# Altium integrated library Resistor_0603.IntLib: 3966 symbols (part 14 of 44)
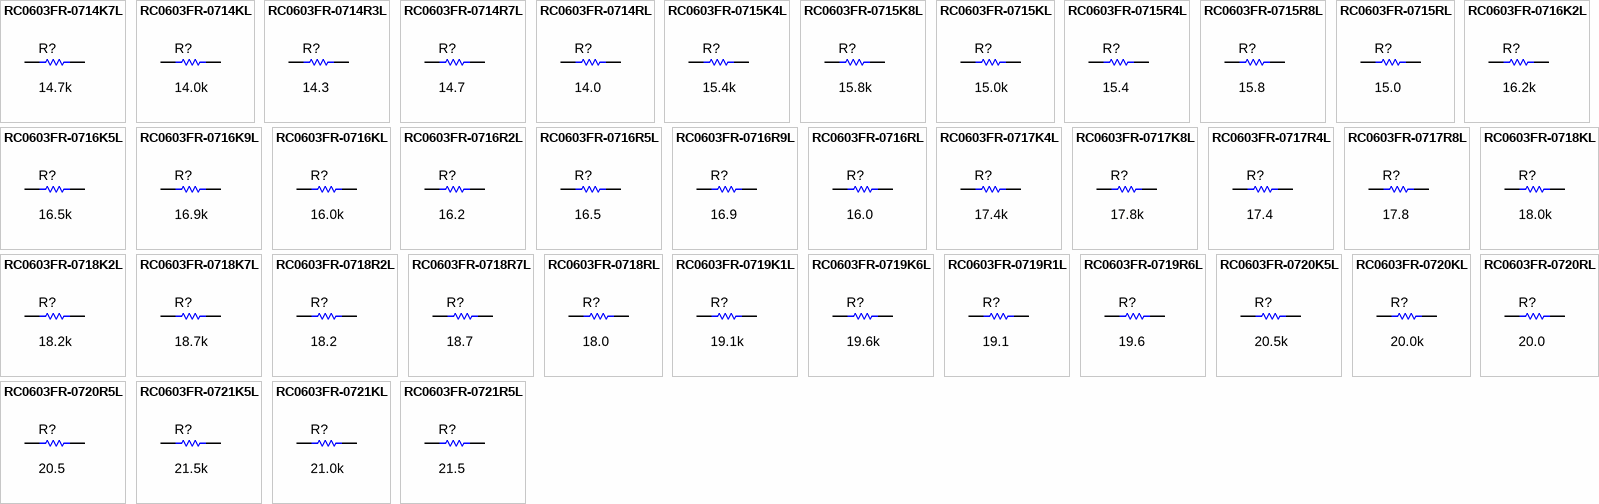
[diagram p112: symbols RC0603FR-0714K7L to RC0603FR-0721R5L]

## RC0603FR-0715K8L
designator R?  ValueDisplayed: 15.8k  (hidden comment: RC0603FR-0715K8L)
RES, 15.8 k, 1%, 0.1 W, 0603; Manufacturer: Yageo America; CompType: Resistor; Value: 15.8k; Res_ohm: 15800; Value_Code: 15k8; Tolerance_%: 1; Power_W: 0.1; Value2: 0.1W; VDC_V: 150; TempCo: 200 ppm/C; SizeArea_mm2: 1.28; SizeX_mm: 1.6; SizeY_mm: 0.8; EIA_Code: E96; U/M: EA; AEC Category: Q200
signal-integrity model Resistor
simulation model Resistor
footprint 0603
footprint 0603M
footprint 0603L
footprint 0603_HV
footprint 0603S
pins: 1, 2

## RC0603FR-0715KL
designator R?  ValueDisplayed: 15.0k  (hidden comment: RC0603FR-0715KL)
RES, 15.0 k, 1%, 0.1 W, 0603; Manufacturer: Yageo America; CompType: Resistor; Value: 15.0k; Res_ohm: 15000; Value_Code: 15k0; Tolerance_%: 1; Power_W: 0.1; Value2: 0.1W; VDC_V: 150; TempCo: 200 ppm/C; SizeArea_mm2: 1.28; SizeX_mm: 1.6; SizeY_mm: 0.8; EIA_Code: E96; U/M: EA; AEC Category: Q200; Green_Lifecycle: Active; Green_REACh: Passed
signal-integrity model Resistor
simulation model Resistor
footprint 0603
footprint 0603M
footprint 0603L
footprint 0603_HV
footprint 0603S
pins: 1, 2

## RC0603FR-0715R4L
designator R?  ValueDisplayed: 15.4  (hidden comment: RC0603FR-0715R4L)
RES, 15.4, 1%, 0.1 W, 0603; Manufacturer: Yageo America; CompType: Resistor; Value: 15.4; Value_Code: 15R4; Tolerance_%: 1; Power_W: 0.1; Value2: 0.1W; VDC_V: 150; TempCo: 200 ppm/C; SizeArea_mm2: 1.28; SizeX_mm: 1.6; SizeY_mm: 0.8; EIA_Code: E96; U/M: EA; AEC Category: Q200
signal-integrity model Resistor
simulation model Resistor
footprint 0603
footprint 0603M
footprint 0603L
footprint 0603_HV
footprint 0603S
pins: 1, 2

## RC0603FR-0715R8L
designator R?  ValueDisplayed: 15.8  (hidden comment: RC0603FR-0715R8L)
RES, 15.8, 1%, 0.1 W, 0603; Manufacturer: Yageo America; CompType: Resistor; Value: 15.8; Value_Code: 15R8; Tolerance_%: 1; Power_W: 0.1; Value2: 0.1W; VDC_V: 150; TempCo: 200 ppm/C; SizeArea_mm2: 1.28; SizeX_mm: 1.6; SizeY_mm: 0.8; EIA_Code: E96; U/M: EA; AEC Category: Q200
signal-integrity model Resistor
simulation model Resistor
footprint 0603
footprint 0603M
footprint 0603L
footprint 0603_HV
footprint 0603S
pins: 1, 2

## RC0603FR-0715RL
designator R?  ValueDisplayed: 15.0  (hidden comment: RC0603FR-0715RL)
RES, 15.0, 1%, 0.1 W, 0603; Manufacturer: Yageo America; CompType: Resistor; Value: 15.0; Res_ohm: 15; Value_Code: 15R0; Tolerance_%: 1; Power_W: 0.1; Value2: 0.1W; VDC_V: 150; TempCo: 200 ppm/C; SizeArea_mm2: 1.28; SizeX_mm: 1.6; SizeY_mm: 0.8; EIA_Code: E96; U/M: EA; AEC Category: Q200; Green_Lifecycle: Not Set; Green_REACh: Incomplete
signal-integrity model Resistor
simulation model Resistor
footprint 0603
footprint 0603M
footprint 0603L
footprint 0603_HV
footprint 0603S
pins: 1, 2

## RC0603FR-0716K2L
designator R?  ValueDisplayed: 16.2k  (hidden comment: RC0603FR-0716K2L)
RES, 16.2 k, 1%, 0.1 W, 0603; Manufacturer: Yageo America; CompType: Resistor; Value: 16.2k; Res_ohm: 16200; Value_Code: 16k2; Tolerance_%: 1; Power_W: 0.1; Value2: 0.1W; VDC_V: 150; TempCo: 200 ppm/C; SizeArea_mm2: 1.28; SizeX_mm: 1.6; SizeY_mm: 0.8; EIA_Code: E96; U/M: EA; AEC Category: Q200; Green_Lifecycle: Active; Green_REACh: Passed
signal-integrity model Resistor
simulation model Resistor
footprint 0603
footprint 0603M
footprint 0603L
footprint 0603_HV
footprint 0603S
pins: 1, 2

## RC0603FR-0716K5L
designator R?  ValueDisplayed: 16.5k  (hidden comment: RC0603FR-0716K5L)
RES, 16.5 k, 1%, 0.1 W, 0603; Manufacturer: Yageo America; CompType: Resistor; Value: 16.5k; Res_ohm: 16500; Value_Code: 16k5; Tolerance_%: 1; Power_W: 0.1; Value2: 0.1W; VDC_V: 150; TempCo: 200 ppm/C; SizeArea_mm2: 1.28; SizeX_mm: 1.6; SizeY_mm: 0.8; EIA_Code: E96; U/M: EA; AEC Category: Q200; Green_Lifecycle: Active; Green_REACh: Passed
signal-integrity model Resistor
simulation model Resistor
footprint 0603
footprint 0603M
footprint 0603L
footprint 0603_HV
footprint 0603S
pins: 1, 2

## RC0603FR-0716K9L
designator R?  ValueDisplayed: 16.9k  (hidden comment: RC0603FR-0716K9L)
RES, 16.9 k, 1%, 0.1 W, 0603; Manufacturer: Yageo America; CompType: Resistor; Value: 16.9k; Res_ohm: 16900; Value_Code: 16k9; Tolerance_%: 1; Power_W: 0.1; Value2: 0.1W; VDC_V: 150; TempCo: 200 ppm/C; SizeArea_mm2: 1.28; SizeX_mm: 1.6; SizeY_mm: 0.8; EIA_Code: E96; U/M: EA; AEC Category: Q200; Green_Lifecycle: Active; Green_REACh: Passed
signal-integrity model Resistor
simulation model Resistor
footprint 0603
footprint 0603M
footprint 0603L
footprint 0603_HV
footprint 0603S
pins: 1, 2

## RC0603FR-0716KL
designator R?  ValueDisplayed: 16.0k  (hidden comment: RC0603FR-0716KL)
RES, 16.0 k, 1%, 0.1 W, 0603; Manufacturer: Yageo America; CompType: Resistor; Value: 16.0k; Res_ohm: 16000; Value_Code: 16k0; Tolerance_%: 1; Power_W: 0.1; Value2: 0.1W; VDC_V: 150; TempCo: 200 ppm/C; SizeArea_mm2: 1.28; SizeX_mm: 1.6; SizeY_mm: 0.8; U/M: EA; AEC Category: Q200; Green_Lifecycle: Active; Green_REACh: Passed
signal-integrity model Resistor
simulation model Resistor
footprint 0603
footprint 0603M
footprint 0603L
footprint 0603_HV
footprint 0603S
pins: 1, 2

## RC0603FR-0716R2L
designator R?  ValueDisplayed: 16.2  (hidden comment: RC0603FR-0716R2L)
RES, 16.2, 1%, 0.1 W, 0603; Manufacturer: Yageo America; CompType: Resistor; Value: 16.2; Value_Code: 16R2; Tolerance_%: 1; Power_W: 0.1; Value2: 0.1W; VDC_V: 150; TempCo: 200 ppm/C; SizeArea_mm2: 1.28; SizeX_mm: 1.6; SizeY_mm: 0.8; EIA_Code: E96; U/M: EA; AEC Category: Q200
signal-integrity model Resistor
simulation model Resistor
footprint 0603
footprint 0603M
footprint 0603L
footprint 0603_HV
footprint 0603S
pins: 1, 2

## RC0603FR-0716R5L
designator R?  ValueDisplayed: 16.5  (hidden comment: RC0603FR-0716R5L)
RES, 16.5, 1%, 0.1 W, 0603; Manufacturer: Yageo America; CompType: Resistor; Value: 16.5; Value_Code: 16R5; Tolerance_%: 1; Power_W: 0.1; Value2: 0.1W; VDC_V: 150; TempCo: 200 ppm/C; SizeArea_mm2: 1.28; SizeX_mm: 1.6; SizeY_mm: 0.8; EIA_Code: E96; U/M: EA; AEC Category: Q200
signal-integrity model Resistor
simulation model Resistor
footprint 0603
footprint 0603M
footprint 0603L
footprint 0603_HV
footprint 0603S
pins: 1, 2

## RC0603FR-0716R9L
designator R?  ValueDisplayed: 16.9  (hidden comment: RC0603FR-0716R9L)
RES, 16.9, 1%, 0.1 W, 0603; Manufacturer: Yageo America; CompType: Resistor; Value: 16.9; Value_Code: 16R9; Tolerance_%: 1; Power_W: 0.1; Value2: 0.1W; VDC_V: 150; TempCo: 200 ppm/C; SizeArea_mm2: 1.28; SizeX_mm: 1.6; SizeY_mm: 0.8; EIA_Code: E96; U/M: EA; AEC Category: Q200
signal-integrity model Resistor
simulation model Resistor
footprint 0603
footprint 0603M
footprint 0603L
footprint 0603_HV
footprint 0603S
pins: 1, 2

## RC0603FR-0716RL
designator R?  ValueDisplayed: 16.0  (hidden comment: RC0603FR-0716RL)
RES, 16.0, 1%, 0.1 W, 0603; Manufacturer: Yageo America; CompType: Resistor; Value: 16.0; Res_ohm: 16; Value_Code: 16R0; Tolerance_%: 1; Power_W: 0.1; Value2: 0.1W; VDC_V: 150; TempCo: 200 ppm/C; SizeArea_mm2: 1.28; SizeX_mm: 1.6; SizeY_mm: 0.8; U/M: EA; AEC Category: Q200
signal-integrity model Resistor
simulation model Resistor
footprint 0603
footprint 0603M
footprint 0603L
footprint 0603_HV
footprint 0603S
pins: 1, 2

## RC0603FR-0717K4L
designator R?  ValueDisplayed: 17.4k  (hidden comment: RC0603FR-0717K4L)
RES, 17.4 k, 1%, 0.1 W, 0603; Manufacturer: Yageo America; CompType: Resistor; Value: 17.4k; Res_ohm: 17400; Value_Code: 17k4; Tolerance_%: 1; Power_W: 0.1; Value2: 0.1W; VDC_V: 150; TempCo: 200 ppm/C; SizeArea_mm2: 1.28; SizeX_mm: 1.6; SizeY_mm: 0.8; EIA_Code: E96; U/M: EA; AEC Category: Q200; Green_Lifecycle: Active; Green_REACh: Passed
signal-integrity model Resistor
simulation model Resistor
footprint 0603
footprint 0603M
footprint 0603L
footprint 0603_HV
footprint 0603S
pins: 1, 2

## RC0603FR-0717K8L
designator R?  ValueDisplayed: 17.8k  (hidden comment: RC0603FR-0717K8L)
RES, 17.8 k, 1%, 0.1 W, 0603; Manufacturer: Yageo America; CompType: Resistor; Value: 17.8k; Res_ohm: 17800; Value_Code: 17k8; Tolerance_%: 1; Power_W: 0.1; Value2: 0.1W; VDC_V: 150; TempCo: 200 ppm/C; SizeArea_mm2: 1.28; SizeX_mm: 1.6; SizeY_mm: 0.8; EIA_Code: E96; U/M: EA; AEC Category: Q200
signal-integrity model Resistor
simulation model Resistor
footprint 0603
footprint 0603M
footprint 0603L
footprint 0603_HV
footprint 0603S
pins: 1, 2

## RC0603FR-0717R4L
designator R?  ValueDisplayed: 17.4  (hidden comment: RC0603FR-0717R4L)
RES, 17.4, 1%, 0.1 W, 0603; Manufacturer: Yageo America; CompType: Resistor; Value: 17.4; Value_Code: 17R4; Tolerance_%: 1; Power_W: 0.1; Value2: 0.1W; VDC_V: 150; TempCo: 200 ppm/C; SizeArea_mm2: 1.28; SizeX_mm: 1.6; SizeY_mm: 0.8; EIA_Code: E96; U/M: EA; AEC Category: Q200; Green_Lifecycle: Active; Green_REACh: Passed
signal-integrity model Resistor
simulation model Resistor
footprint 0603
footprint 0603M
footprint 0603L
footprint 0603_HV
footprint 0603S
pins: 1, 2

## RC0603FR-0717R8L
designator R?  ValueDisplayed: 17.8  (hidden comment: RC0603FR-0717R8L)
RES, 17.8, 1%, 0.1 W, 0603; Manufacturer: Yageo America; CompType: Resistor; Value: 17.8; Value_Code: 17R8; Tolerance_%: 1; Power_W: 0.1; Value2: 0.1W; VDC_V: 150; TempCo: 200 ppm/C; SizeArea_mm2: 1.28; SizeX_mm: 1.6; SizeY_mm: 0.8; EIA_Code: E96; U/M: EA; AEC Category: Q200
signal-integrity model Resistor
simulation model Resistor
footprint 0603
footprint 0603M
footprint 0603L
footprint 0603_HV
footprint 0603S
pins: 1, 2

## RC0603FR-0718K2L
designator R?  ValueDisplayed: 18.2k  (hidden comment: RC0603FR-0718K2L)
RES, 18.2 k, 1%, 0.1 W, 0603; Manufacturer: Yageo America; CompType: Resistor; Value: 18.2k; Res_ohm: 18200; Value_Code: 18k2; Tolerance_%: 1; Power_W: 0.1; Value2: 0.1W; VDC_V: 150; TempCo: 200 ppm/C; SizeArea_mm2: 1.28; SizeX_mm: 1.6; SizeY_mm: 0.8; EIA_Code: E96; U/M: EA; AEC Category: Q200; Green_Lifecycle: Active; Green_REACh: Passed
signal-integrity model Resistor
simulation model Resistor
footprint 0603
footprint 0603M
footprint 0603L
footprint 0603_HV
footprint 0603S
pins: 1, 2

## RC0603FR-0718K7L
designator R?  ValueDisplayed: 18.7k  (hidden comment: RC0603FR-0718K7L)
RES, 18.7 k, 1%, 0.1 W, 0603; Manufacturer: Yageo America; CompType: Resistor; Value: 18.7k; Res_ohm: 18700; Value_Code: 18k7; Tolerance_%: 1; Power_W: 0.1; Value2: 0.1W; VDC_V: 150; TempCo: 200 ppm/C; SizeArea_mm2: 1.28; SizeX_mm: 1.6; SizeY_mm: 0.8; EIA_Code: E96; U/M: EA; AEC Category: Q200
signal-integrity model Resistor
simulation model Resistor
footprint 0603
footprint 0603M
footprint 0603L
footprint 0603_HV
footprint 0603S
pins: 1, 2

## RC0603FR-0718KL
designator R?  ValueDisplayed: 18.0k  (hidden comment: RC0603FR-0718KL)
RES, 18.0 k, 1%, 0.1 W, 0603; Manufacturer: Yageo America; CompType: Resistor; Value: 18.0k; Res_ohm: 18000; Value_Code: 18k0; Tolerance_%: 1; Power_W: 0.1; Value2: 0.1W; VDC_V: 150; TempCo: 200 ppm/C; SizeArea_mm2: 1.28; SizeX_mm: 1.6; SizeY_mm: 0.8; U/M: EA; AEC Category: Q200; Green_Lifecycle: Active; Green_REACh: Passed
signal-integrity model Resistor
simulation model Resistor
footprint 0603
footprint 0603M
footprint 0603L
footprint 0603_HV
footprint 0603S
pins: 1, 2

## RC0603FR-0718R2L
designator R?  ValueDisplayed: 18.2  (hidden comment: RC0603FR-0718R2L)
RES, 18.2, 1%, 0.1 W, 0603; Manufacturer: Yageo America; CompType: Resistor; Value: 18.2; Value_Code: 18R2; Tolerance_%: 1; Power_W: 0.1; Value2: 0.1W; VDC_V: 150; TempCo: 200 ppm/C; SizeArea_mm2: 1.28; SizeX_mm: 1.6; SizeY_mm: 0.8; EIA_Code: E96; U/M: EA; AEC Category: Q200
signal-integrity model Resistor
simulation model Resistor
footprint 0603
footprint 0603M
footprint 0603L
footprint 0603_HV
footprint 0603S
pins: 1, 2

## RC0603FR-0718R7L
designator R?  ValueDisplayed: 18.7  (hidden comment: RC0603FR-0718R7L)
RES, 18.7, 1%, 0.1 W, 0603; Manufacturer: Yageo America; CompType: Resistor; Value: 18.7; Value_Code: 18R7; Tolerance_%: 1; Power_W: 0.1; Value2: 0.1W; VDC_V: 150; TempCo: 200 ppm/C; SizeArea_mm2: 1.28; SizeX_mm: 1.6; SizeY_mm: 0.8; EIA_Code: E96; U/M: EA; AEC Category: Q200
signal-integrity model Resistor
simulation model Resistor
footprint 0603
footprint 0603M
footprint 0603L
footprint 0603_HV
footprint 0603S
pins: 1, 2

## RC0603FR-0718RL
designator R?  ValueDisplayed: 18.0  (hidden comment: RC0603FR-0718RL)
RES, 18.0, 1%, 0.1 W, 0603; Manufacturer: Yageo America; CompType: Resistor; Value: 18.0; Res_ohm: 18; Value_Code: 18R0; Tolerance_%: 1; Power_W: 0.1; Value2: 0.1W; VDC_V: 150; TempCo: 200 ppm/C; SizeArea_mm2: 1.28; SizeX_mm: 1.6; SizeY_mm: 0.8; U/M: EA; AEC Category: Q200
signal-integrity model Resistor
simulation model Resistor
footprint 0603
footprint 0603M
footprint 0603L
footprint 0603_HV
footprint 0603S
pins: 1, 2

## RC0603FR-0719K1L
designator R?  ValueDisplayed: 19.1k  (hidden comment: RC0603FR-0719K1L)
RES, 19.1 k, 1%, 0.1 W, 0603; Manufacturer: Yageo America; CompType: Resistor; Value: 19.1k; Res_ohm: 19100; Value_Code: 19k1; Tolerance_%: 1; Power_W: 0.1; Value2: 0.1W; VDC_V: 150; TempCo: 200 ppm/C; SizeArea_mm2: 1.28; SizeX_mm: 1.6; SizeY_mm: 0.8; EIA_Code: E96; U/M: EA; AEC Category: Q200
signal-integrity model Resistor
simulation model Resistor
footprint 0603
footprint 0603M
footprint 0603L
footprint 0603_HV
footprint 0603S
pins: 1, 2

## RC0603FR-0719K6L
designator R?  ValueDisplayed: 19.6k  (hidden comment: RC0603FR-0719K6L)
RES, 19.6 k, 1%, 0.1 W, 0603; Manufacturer: Yageo America; CompType: Resistor; Value: 19.6k; Res_ohm: 19600; Value_Code: 19k6; Tolerance_%: 1; Power_W: 0.1; Value2: 0.1W; VDC_V: 150; TempCo: 200 ppm/C; SizeArea_mm2: 1.28; SizeX_mm: 1.6; SizeY_mm: 0.8; EIA_Code: E96; U/M: EA; AEC Category: Q200
signal-integrity model Resistor
simulation model Resistor
footprint 0603
footprint 0603M
footprint 0603L
footprint 0603_HV
footprint 0603S
pins: 1, 2

## RC0603FR-0719R1L
designator R?  ValueDisplayed: 19.1  (hidden comment: RC0603FR-0719R1L)
RES, 19.1, 1%, 0.1 W, 0603; Manufacturer: Yageo America; CompType: Resistor; Value: 19.1; Value_Code: 19R1; Tolerance_%: 1; Power_W: 0.1; Value2: 0.1W; VDC_V: 150; TempCo: 200 ppm/C; SizeArea_mm2: 1.28; SizeX_mm: 1.6; SizeY_mm: 0.8; EIA_Code: E96; U/M: EA; AEC Category: Q200
signal-integrity model Resistor
simulation model Resistor
footprint 0603
footprint 0603M
footprint 0603L
footprint 0603_HV
footprint 0603S
pins: 1, 2

## RC0603FR-0719R6L
designator R?  ValueDisplayed: 19.6  (hidden comment: RC0603FR-0719R6L)
RES, 19.6, 1%, 0.1 W, 0603; Manufacturer: Yageo America; CompType: Resistor; Value: 19.6; Value_Code: 19R6; Tolerance_%: 1; Power_W: 0.1; Value2: 0.1W; VDC_V: 150; TempCo: 200 ppm/C; SizeArea_mm2: 1.28; SizeX_mm: 1.6; SizeY_mm: 0.8; EIA_Code: E96; U/M: EA; AEC Category: Q200
signal-integrity model Resistor
simulation model Resistor
footprint 0603
footprint 0603M
footprint 0603L
footprint 0603_HV
footprint 0603S
pins: 1, 2

## RC0603FR-0720K5L
designator R?  ValueDisplayed: 20.5k  (hidden comment: RC0603FR-0720K5L)
RES, 20.5 k, 1%, 0.1 W, 0603; Manufacturer: Yageo America; CompType: Resistor; Value: 20.5k; Res_ohm: 20500; Value_Code: 20k5; Tolerance_%: 1; Power_W: 0.1; Value2: 0.1W; VDC_V: 150; TempCo: 200 ppm/C; SizeArea_mm2: 1.28; SizeX_mm: 1.6; SizeY_mm: 0.8; EIA_Code: E96; U/M: EA; AEC Category: Q200; Green_Lifecycle: Active; Green_REACh: Passed
signal-integrity model Resistor
simulation model Resistor
footprint 0603
footprint 0603M
footprint 0603L
footprint 0603_HV
footprint 0603S
pins: 1, 2

## RC0603FR-0720KL
designator R?  ValueDisplayed: 20.0k  (hidden comment: RC0603FR-0720KL)
RES, 20.0 k, 1%, 0.1 W, 0603; Manufacturer: Yageo America; CompType: Resistor; Value: 20.0k; Res_ohm: 20000; Value_Code: 20k0; Tolerance_%: 1; Power_W: 0.1; Value2: 0.1W; VDC_V: 150; TempCo: 200 ppm/C; SizeArea_mm2: 1.28; SizeX_mm: 1.6; SizeY_mm: 0.8; EIA_Code: E96; U/M: EA; AEC Category: Q200; Green_Lifecycle: Active; Green_REACh: Passed
signal-integrity model Resistor
simulation model Resistor
footprint 0603
footprint 0603M
footprint 0603L
footprint 0603_HV
footprint 0603S
pins: 1, 2

## RC0603FR-0720R5L
designator R?  ValueDisplayed: 20.5  (hidden comment: RC0603FR-0720R5L)
RES, 20.5, 1%, 0.1 W, 0603; Manufacturer: Yageo America; CompType: Resistor; Value: 20.5; Value_Code: 20R5; Tolerance_%: 1; Power_W: 0.1; Value2: 0.1W; VDC_V: 150; TempCo: 200 ppm/C; SizeArea_mm2: 1.28; SizeX_mm: 1.6; SizeY_mm: 0.8; EIA_Code: E96; U/M: EA; AEC Category: Q200
signal-integrity model Resistor
simulation model Resistor
footprint 0603
footprint 0603M
footprint 0603L
footprint 0603_HV
footprint 0603S
pins: 1, 2

## RC0603FR-0720RL
designator R?  ValueDisplayed: 20.0  (hidden comment: RC0603FR-0720RL)
RES, 20.0, 1%, 0.1 W, 0603; Manufacturer: Yageo America; CompType: Resistor; Value: 20.0; Res_ohm: 20; Value_Code: 20R0; Tolerance_%: 1; Power_W: 0.1; Value2: 0.1W; VDC_V: 150; TempCo: 200 ppm/C; SizeArea_mm2: 1.28; SizeX_mm: 1.6; SizeY_mm: 0.8; EIA_Code: E96; U/M: EA; AEC Category: Q200; Green_Lifecycle: Active; Green_REACh: Passed
signal-integrity model Resistor
simulation model Resistor
footprint 0603
footprint 0603M
footprint 0603L
footprint 0603_HV
footprint 0603S
pins: 1, 2

## RC0603FR-0721K5L
designator R?  ValueDisplayed: 21.5k  (hidden comment: RC0603FR-0721K5L)
RES, 21.5 k, 1%, 0.1 W, 0603; Manufacturer: Yageo America; CompType: Resistor; Value: 21.5k; Res_ohm: 21500; Value_Code: 21k5; Tolerance_%: 1; Power_W: 0.1; Value2: 0.1W; VDC_V: 150; TempCo: 200 ppm/C; SizeArea_mm2: 1.28; SizeX_mm: 1.6; SizeY_mm: 0.8; EIA_Code: E96; U/M: EA; AEC Category: Q200; Green_Lifecycle: Active; Green_REACh: Passed
signal-integrity model Resistor
simulation model Resistor
footprint 0603
footprint 0603M
footprint 0603L
footprint 0603_HV
footprint 0603S
pins: 1, 2

## RC0603FR-0721KL
designator R?  ValueDisplayed: 21.0k  (hidden comment: RC0603FR-0721KL)
RES, 21.0 k, 1%, 0.1 W, 0603; Manufacturer: Yageo America; CompType: Resistor; Value: 21.0k; Res_ohm: 21000; Value_Code: 21k0; Tolerance_%: 1; Power_W: 0.1; Value2: 0.1W; VDC_V: 150; TempCo: 200 ppm/C; SizeArea_mm2: 1.28; SizeX_mm: 1.6; SizeY_mm: 0.8; EIA_Code: E96; U/M: EA; AEC Category: Q200
signal-integrity model Resistor
simulation model Resistor
footprint 0603
footprint 0603M
footprint 0603L
footprint 0603_HV
footprint 0603S
pins: 1, 2

## RC0603FR-0721R5L
designator R?  ValueDisplayed: 21.5  (hidden comment: RC0603FR-0721R5L)
RES, 21.5, 1%, 0.1 W, 0603; Manufacturer: Yageo America; CompType: Resistor; Value: 21.5; Value_Code: 21R5; Tolerance_%: 1; Power_W: 0.1; Value2: 0.1W; VDC_V: 150; TempCo: 200 ppm/C; SizeArea_mm2: 1.28; SizeX_mm: 1.6; SizeY_mm: 0.8; EIA_Code: E96; U/M: EA; AEC Category: Q200; Green_Lifecycle: Active; Green_REACh: Passed
signal-integrity model Resistor
simulation model Resistor
footprint 0603
footprint 0603M
footprint 0603L
footprint 0603_HV
footprint 0603S
pins: 1, 2

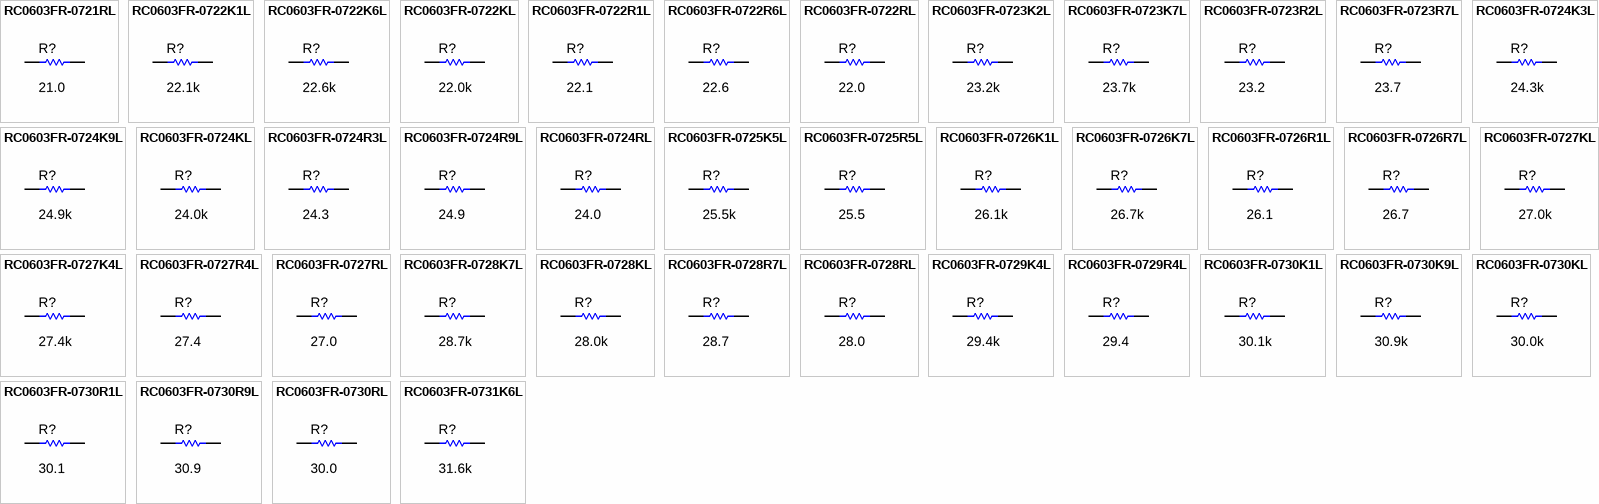
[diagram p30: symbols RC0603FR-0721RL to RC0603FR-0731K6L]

## RC0603FR-0721RL
designator R?  ValueDisplayed: 21.0  (hidden comment: RC0603FR-0721RL)
RES, 21.0, 1%, 0.1 W, 0603; Manufacturer: Yageo America; CompType: Resistor; Value: 21.0; Res_ohm: 21; Value_Code: 21R0; Tolerance_%: 1; Power_W: 0.1; Value2: 0.1W; VDC_V: 150; TempCo: 200 ppm/C; SizeArea_mm2: 1.28; SizeX_mm: 1.6; SizeY_mm: 0.8; EIA_Code: E96; U/M: EA; AEC Category: Q200
signal-integrity model Resistor
simulation model Resistor
footprint 0603
footprint 0603M
footprint 0603L
footprint 0603_HV
footprint 0603S
pins: 1, 2

## RC0603FR-0722K1L
designator R?  ValueDisplayed: 22.1k  (hidden comment: RC0603FR-0722K1L)
RES, 22.1 k, 1%, 0.1 W, 0603; Manufacturer: Yageo America; CompType: Resistor; Value: 22.1k; Res_ohm: 22100; Value_Code: 22k1; Tolerance_%: 1; Power_W: 0.1; Value2: 0.1W; VDC_V: 150; TempCo: 200 ppm/C; SizeArea_mm2: 1.28; SizeX_mm: 1.6; SizeY_mm: 0.8; EIA_Code: E96; U/M: EA; AEC Category: Q200; Green_Lifecycle: Active; Green_REACh: Passed
signal-integrity model Resistor
simulation model Resistor
footprint 0603
footprint 0603M
footprint 0603L
footprint 0603_HV
footprint 0603S
pins: 1, 2

## RC0603FR-0722K6L
designator R?  ValueDisplayed: 22.6k  (hidden comment: RC0603FR-0722K6L)
RES, 22.6 k, 1%, 0.1 W, 0603; Manufacturer: Yageo America; CompType: Resistor; Value: 22.6k; Res_ohm: 22600; Value_Code: 22k6; Tolerance_%: 1; Power_W: 0.1; Value2: 0.1W; VDC_V: 150; TempCo: 200 ppm/C; SizeArea_mm2: 1.28; SizeX_mm: 1.6; SizeY_mm: 0.8; EIA_Code: E96; U/M: EA; AEC Category: Q200; Green_Lifecycle: Active; Green_REACh: Passed
signal-integrity model Resistor
simulation model Resistor
footprint 0603
footprint 0603M
footprint 0603L
footprint 0603_HV
footprint 0603S
pins: 1, 2

## RC0603FR-0722KL
designator R?  ValueDisplayed: 22.0k  (hidden comment: RC0603FR-0722KL)
RES, 22.0 k, 1%, 0.1 W, 0603; Manufacturer: Yageo America; CompType: Resistor; Value: 22.0k; Res_ohm: 22000; Value_Code: 22k0; Tolerance_%: 1; Power_W: 0.1; Value2: 0.1W; VDC_V: 150; TempCo: 200 ppm/C; SizeArea_mm2: 1.28; SizeX_mm: 1.6; SizeY_mm: 0.8; U/M: EA; AEC Category: Q200; Green_Lifecycle: Active; Green_REACh: Passed
signal-integrity model Resistor
simulation model Resistor
footprint 0603
footprint 0603M
footprint 0603L
footprint 0603_HV
footprint 0603S
pins: 1, 2

## RC0603FR-0722R1L
designator R?  ValueDisplayed: 22.1  (hidden comment: RC0603FR-0722R1L)
RES, 22.1, 1%, 0.1 W, 0603; Manufacturer: Yageo America; CompType: Resistor; Value: 22.1; Value_Code: 22R1; Tolerance_%: 1; Power_W: 0.1; Value2: 0.1W; VDC_V: 150; TempCo: 200 ppm/C; SizeArea_mm2: 1.28; SizeX_mm: 1.6; SizeY_mm: 0.8; EIA_Code: E96; U/M: EA; AEC Category: Q200; Green_Lifecycle: Active; Green_REACh: Passed
signal-integrity model Resistor
simulation model Resistor
footprint 0603
footprint 0603M
footprint 0603L
footprint 0603_HV
footprint 0603S
pins: 1, 2

## RC0603FR-0722R6L
designator R?  ValueDisplayed: 22.6  (hidden comment: RC0603FR-0722R6L)
RES, 22.6, 1%, 0.1 W, 0603; Manufacturer: Yageo America; CompType: Resistor; Value: 22.6; Value_Code: 22R6; Tolerance_%: 1; Power_W: 0.1; Value2: 0.1W; VDC_V: 150; TempCo: 200 ppm/C; SizeArea_mm2: 1.28; SizeX_mm: 1.6; SizeY_mm: 0.8; EIA_Code: E96; U/M: EA; AEC Category: Q200
signal-integrity model Resistor
simulation model Resistor
footprint 0603
footprint 0603M
footprint 0603L
footprint 0603_HV
footprint 0603S
pins: 1, 2

## RC0603FR-0722RL
designator R?  ValueDisplayed: 22.0  (hidden comment: RC0603FR-0722RL)
RES, 22.0, 1%, 0.1 W, 0603; Manufacturer: Yageo America; CompType: Resistor; Value: 22.0; Res_ohm: 22; Value_Code: 22R0; Tolerance_%: 1; Power_W: 0.1; Value2: 0.1W; VDC_V: 150; TempCo: 200 ppm/C; SizeArea_mm2: 1.28; SizeX_mm: 1.6; SizeY_mm: 0.8; U/M: EA; AEC Category: Q200; Green_Lifecycle: Active; Green_REACh: Passed
signal-integrity model Resistor
simulation model Resistor
footprint 0603
footprint 0603M
footprint 0603L
footprint 0603_HV
footprint 0603S
pins: 1, 2

## RC0603FR-0723K2L
designator R?  ValueDisplayed: 23.2k  (hidden comment: RC0603FR-0723K2L)
RES, 23.2 k, 1%, 0.1 W, 0603; Manufacturer: Yageo America; CompType: Resistor; Value: 23.2k; Res_ohm: 23200; Value_Code: 23k2; Tolerance_%: 1; Power_W: 0.1; Value2: 0.1W; VDC_V: 150; TempCo: 200 ppm/C; SizeArea_mm2: 1.28; SizeX_mm: 1.6; SizeY_mm: 0.8; EIA_Code: E96; U/M: EA; AEC Category: Q200; Green_Lifecycle: Active; Green_REACh: Passed
signal-integrity model Resistor
simulation model Resistor
footprint 0603
footprint 0603M
footprint 0603L
footprint 0603_HV
footprint 0603S
pins: 1, 2

## RC0603FR-0723K7L
designator R?  ValueDisplayed: 23.7k  (hidden comment: RC0603FR-0723K7L)
RES, 23.7 k, 1%, 0.1 W, 0603; Manufacturer: Yageo America; CompType: Resistor; Value: 23.7k; Res_ohm: 23700; Value_Code: 23k7; Tolerance_%: 1; Power_W: 0.1; Value2: 0.1W; VDC_V: 150; TempCo: 200 ppm/C; SizeArea_mm2: 1.28; SizeX_mm: 1.6; SizeY_mm: 0.8; EIA_Code: E96; U/M: EA; AEC Category: Q200; Green_Lifecycle: Active; Green_REACh: Passed
signal-integrity model Resistor
simulation model Resistor
footprint 0603
footprint 0603M
footprint 0603L
footprint 0603_HV
footprint 0603S
pins: 1, 2

## RC0603FR-0723R2L
designator R?  ValueDisplayed: 23.2  (hidden comment: RC0603FR-0723R2L)
RES, 23.2, 1%, 0.1 W, 0603; Manufacturer: Yageo America; CompType: Resistor; Value: 23.2; Value_Code: 23R2; Tolerance_%: 1; Power_W: 0.1; Value2: 0.1W; VDC_V: 150; TempCo: 200 ppm/C; SizeArea_mm2: 1.28; SizeX_mm: 1.6; SizeY_mm: 0.8; EIA_Code: E96; U/M: EA; AEC Category: Q200
signal-integrity model Resistor
simulation model Resistor
footprint 0603
footprint 0603M
footprint 0603L
footprint 0603_HV
footprint 0603S
pins: 1, 2

## RC0603FR-0723R7L
designator R?  ValueDisplayed: 23.7  (hidden comment: RC0603FR-0723R7L)
RES, 23.7, 1%, 0.1 W, 0603; Manufacturer: Yageo America; CompType: Resistor; Value: 23.7; Value_Code: 23R7; Tolerance_%: 1; Power_W: 0.1; Value2: 0.1W; VDC_V: 150; TempCo: 200 ppm/C; SizeArea_mm2: 1.28; SizeX_mm: 1.6; SizeY_mm: 0.8; EIA_Code: E96; U/M: EA; AEC Category: Q200
signal-integrity model Resistor
simulation model Resistor
footprint 0603
footprint 0603M
footprint 0603L
footprint 0603_HV
footprint 0603S
pins: 1, 2

## RC0603FR-0724K3L
designator R?  ValueDisplayed: 24.3k  (hidden comment: RC0603FR-0724K3L)
RES, 24.3 k, 1%, 0.1 W, 0603; Manufacturer: Yageo America; CompType: Resistor; Value: 24.3k; Res_ohm: 24300; Value_Code: 24k3; Tolerance_%: 1; Power_W: 0.1; Value2: 0.1W; VDC_V: 150; TempCo: 200 ppm/C; SizeArea_mm2: 1.28; SizeX_mm: 1.6; SizeY_mm: 0.8; EIA_Code: E96; U/M: EA; AEC Category: Q200
signal-integrity model Resistor
simulation model Resistor
footprint 0603
footprint 0603M
footprint 0603L
footprint 0603_HV
footprint 0603S
pins: 1, 2

## RC0603FR-0724K9L
designator R?  ValueDisplayed: 24.9k  (hidden comment: RC0603FR-0724K9L)
RES, 24.9 k, 1%, 0.1 W, 0603; Manufacturer: Yageo America; CompType: Resistor; Value: 24.9k; Res_ohm: 24900; Value_Code: 24k9; Tolerance_%: 1; Power_W: 0.1; Value2: 0.1W; VDC_V: 150; TempCo: 200 ppm/C; SizeArea_mm2: 1.28; SizeX_mm: 1.6; SizeY_mm: 0.8; EIA_Code: E96; U/M: EA; AEC Category: Q200; Green_Lifecycle: Active; Green_REACh: Passed
signal-integrity model Resistor
simulation model Resistor
footprint 0603
footprint 0603M
footprint 0603L
footprint 0603_HV
footprint 0603S
pins: 1, 2

## RC0603FR-0724KL
designator R?  ValueDisplayed: 24.0k  (hidden comment: RC0603FR-0724KL)
RES, 24.0 k, 1%, 0.1 W, 0603; Manufacturer: Yageo America; CompType: Resistor; Value: 24.0k; Res_ohm: 24000; Value_Code: 24k0; Tolerance_%: 1; Power_W: 0.1; Value2: 0.1W; VDC_V: 150; TempCo: 200 ppm/C; SizeArea_mm2: 1.28; SizeX_mm: 1.6; SizeY_mm: 0.8; U/M: EA; AEC Category: Q200; Green_Lifecycle: Active; Green_REACh: Passed
signal-integrity model Resistor
simulation model Resistor
footprint 0603
footprint 0603M
footprint 0603L
footprint 0603_HV
footprint 0603S
pins: 1, 2

## RC0603FR-0724R3L
designator R?  ValueDisplayed: 24.3  (hidden comment: RC0603FR-0724R3L)
RES, 24.3, 1%, 0.1 W, 0603; Manufacturer: Yageo America; CompType: Resistor; Value: 24.3; Value_Code: 24R3; Tolerance_%: 1; Power_W: 0.1; Value2: 0.1W; VDC_V: 150; TempCo: 200 ppm/C; SizeArea_mm2: 1.28; SizeX_mm: 1.6; SizeY_mm: 0.8; EIA_Code: E96; U/M: EA; AEC Category: Q200; Green_Lifecycle: Active; Green_REACh: Passed
signal-integrity model Resistor
simulation model Resistor
footprint 0603
footprint 0603M
footprint 0603L
footprint 0603_HV
footprint 0603S
pins: 1, 2

## RC0603FR-0724R9L
designator R?  ValueDisplayed: 24.9  (hidden comment: RC0603FR-0724R9L)
RES, 24.9, 1%, 0.1 W, 0603; Manufacturer: Yageo America; CompType: Resistor; Value: 24.9; Value_Code: 24R9; Tolerance_%: 1; Power_W: 0.1; Value2: 0.1W; VDC_V: 150; TempCo: 200 ppm/C; SizeArea_mm2: 1.28; SizeX_mm: 1.6; SizeY_mm: 0.8; EIA_Code: E96; U/M: EA; AEC Category: Q200
signal-integrity model Resistor
simulation model Resistor
footprint 0603
footprint 0603M
footprint 0603L
footprint 0603_HV
footprint 0603S
pins: 1, 2

## RC0603FR-0724RL
designator R?  ValueDisplayed: 24.0  (hidden comment: RC0603FR-0724RL)
RES, 24.0, 1%, 0.1 W, 0603; Manufacturer: Yageo America; CompType: Resistor; Value: 24.0; Res_ohm: 24; Value_Code: 24R0; Tolerance_%: 1; Power_W: 0.1; Value2: 0.1W; VDC_V: 150; TempCo: 200 ppm/C; SizeArea_mm2: 1.28; SizeX_mm: 1.6; SizeY_mm: 0.8; U/M: EA; AEC Category: Q200
signal-integrity model Resistor
simulation model Resistor
footprint 0603
footprint 0603M
footprint 0603L
footprint 0603_HV
footprint 0603S
pins: 1, 2

## RC0603FR-0725K5L
designator R?  ValueDisplayed: 25.5k  (hidden comment: RC0603FR-0725K5L)
RES, 25.5 k, 1%, 0.1 W, 0603; Manufacturer: Yageo America; CompType: Resistor; Value: 25.5k; Res_ohm: 25500; Value_Code: 25k5; Tolerance_%: 1; Power_W: 0.1; Value2: 0.1W; VDC_V: 150; TempCo: 200 ppm/C; SizeArea_mm2: 1.28; SizeX_mm: 1.6; SizeY_mm: 0.8; EIA_Code: E96; U/M: EA; AEC Category: Q200; Green_Lifecycle: Active; Green_REACh: Passed
signal-integrity model Resistor
simulation model Resistor
footprint 0603
footprint 0603M
footprint 0603L
footprint 0603_HV
footprint 0603S
pins: 1, 2

## RC0603FR-0725R5L
designator R?  ValueDisplayed: 25.5  (hidden comment: RC0603FR-0725R5L)
RES, 25.5, 1%, 0.1 W, 0603; Manufacturer: Yageo America; CompType: Resistor; Value: 25.5; Value_Code: 25R5; Tolerance_%: 1; Power_W: 0.1; Value2: 0.1W; VDC_V: 150; TempCo: 200 ppm/C; SizeArea_mm2: 1.28; SizeX_mm: 1.6; SizeY_mm: 0.8; EIA_Code: E96; U/M: EA; AEC Category: Q200
signal-integrity model Resistor
simulation model Resistor
footprint 0603
footprint 0603M
footprint 0603L
footprint 0603_HV
footprint 0603S
pins: 1, 2

## RC0603FR-0726K1L
designator R?  ValueDisplayed: 26.1k  (hidden comment: RC0603FR-0726K1L)
RES, 26.1 k, 1%, 0.1 W, 0603; Manufacturer: Yageo America; CompType: Resistor; Value: 26.1k; Res_ohm: 26100; Value_Code: 26k1; Tolerance_%: 1; Power_W: 0.1; Value2: 0.1W; VDC_V: 150; TempCo: 200 ppm/C; SizeArea_mm2: 1.28; SizeX_mm: 1.6; SizeY_mm: 0.8; EIA_Code: E96; U/M: EA; AEC Category: Q200
signal-integrity model Resistor
simulation model Resistor
footprint 0603
footprint 0603M
footprint 0603L
footprint 0603_HV
footprint 0603S
pins: 1, 2

## RC0603FR-0726K7L
designator R?  ValueDisplayed: 26.7k  (hidden comment: RC0603FR-0726K7L)
RES, 26.7 k, 1%, 0.1 W, 0603; Manufacturer: Yageo America; CompType: Resistor; Value: 26.7k; Res_ohm: 26700; Value_Code: 26k7; Tolerance_%: 1; Power_W: 0.1; Value2: 0.1W; VDC_V: 150; TempCo: 200 ppm/C; SizeArea_mm2: 1.28; SizeX_mm: 1.6; SizeY_mm: 0.8; EIA_Code: E96; U/M: EA; AEC Category: Q200; Green_Lifecycle: Active; Green_REACh: Passed
signal-integrity model Resistor
simulation model Resistor
footprint 0603
footprint 0603M
footprint 0603L
footprint 0603_HV
footprint 0603S
pins: 1, 2

## RC0603FR-0726R1L
designator R?  ValueDisplayed: 26.1  (hidden comment: RC0603FR-0726R1L)
RES, 26.1, 1%, 0.1 W, 0603; Manufacturer: Yageo America; CompType: Resistor; Value: 26.1; Value_Code: 26R1; Tolerance_%: 1; Power_W: 0.1; Value2: 0.1W; VDC_V: 150; TempCo: 200 ppm/C; SizeArea_mm2: 1.28; SizeX_mm: 1.6; SizeY_mm: 0.8; EIA_Code: E96; U/M: EA; AEC Category: Q200
signal-integrity model Resistor
simulation model Resistor
footprint 0603
footprint 0603M
footprint 0603L
footprint 0603_HV
footprint 0603S
pins: 1, 2

## RC0603FR-0726R7L
designator R?  ValueDisplayed: 26.7  (hidden comment: RC0603FR-0726R7L)
RES, 26.7, 1%, 0.1 W, 0603; Manufacturer: Yageo America; CompType: Resistor; Value: 26.7; Value_Code: 26R7; Tolerance_%: 1; Power_W: 0.1; Value2: 0.1W; VDC_V: 150; TempCo: 200 ppm/C; SizeArea_mm2: 1.28; SizeX_mm: 1.6; SizeY_mm: 0.8; EIA_Code: E96; U/M: EA; AEC Category: Q200
signal-integrity model Resistor
simulation model Resistor
footprint 0603
footprint 0603M
footprint 0603L
footprint 0603_HV
footprint 0603S
pins: 1, 2

## RC0603FR-0727K4L
designator R?  ValueDisplayed: 27.4k  (hidden comment: RC0603FR-0727K4L)
RES, 27.4 k, 1%, 0.1 W, 0603; Manufacturer: Yageo America; CompType: Resistor; Value: 27.4k; Res_ohm: 27400; Value_Code: 27k4; Tolerance_%: 1; Power_W: 0.1; Value2: 0.1W; VDC_V: 150; TempCo: 200 ppm/C; SizeArea_mm2: 1.28; SizeX_mm: 1.6; SizeY_mm: 0.8; EIA_Code: E96; U/M: EA; AEC Category: Q200
signal-integrity model Resistor
simulation model Resistor
footprint 0603
footprint 0603M
footprint 0603L
footprint 0603_HV
footprint 0603S
pins: 1, 2

## RC0603FR-0727KL
designator R?  ValueDisplayed: 27.0k  (hidden comment: RC0603FR-0727KL)
RES, 27.0 k, 1%, 0.1 W, 0603; Manufacturer: Yageo America; CompType: Resistor; Value: 27.0k; Res_ohm: 27000; Value_Code: 27k0; Tolerance_%: 1; Power_W: 0.1; Value2: 0.1W; VDC_V: 150; TempCo: 200 ppm/C; SizeArea_mm2: 1.28; SizeX_mm: 1.6; SizeY_mm: 0.8; U/M: EA; AEC Category: Q200; Green_Lifecycle: Active; Green_REACh: Passed
signal-integrity model Resistor
simulation model Resistor
footprint 0603
footprint 0603M
footprint 0603L
footprint 0603_HV
footprint 0603S
pins: 1, 2

## RC0603FR-0727R4L
designator R?  ValueDisplayed: 27.4  (hidden comment: RC0603FR-0727R4L)
RES, 27.4, 1%, 0.1 W, 0603; Manufacturer: Yageo America; CompType: Resistor; Value: 27.4; Value_Code: 27R4; Tolerance_%: 1; Power_W: 0.1; Value2: 0.1W; VDC_V: 150; TempCo: 200 ppm/C; SizeArea_mm2: 1.28; SizeX_mm: 1.6; SizeY_mm: 0.8; EIA_Code: E96; U/M: EA; AEC Category: Q200; Green_Lifecycle: Active; Green_REACh: Passed
signal-integrity model Resistor
simulation model Resistor
footprint 0603
footprint 0603M
footprint 0603L
footprint 0603_HV
footprint 0603S
pins: 1, 2

## RC0603FR-0727RL
designator R?  ValueDisplayed: 27.0  (hidden comment: RC0603FR-0727RL)
RES, 27.0, 1%, 0.1 W, 0603; Manufacturer: Yageo America; CompType: Resistor; Value: 27.0; Res_ohm: 27; Value_Code: 27R0; Tolerance_%: 1; Power_W: 0.1; Value2: 0.1W; VDC_V: 150; TempCo: 200 ppm/C; SizeArea_mm2: 1.28; SizeX_mm: 1.6; SizeY_mm: 0.8; U/M: EA; AEC Category: Q200; Green_Lifecycle: Active; Green_REACh: Passed
signal-integrity model Resistor
simulation model Resistor
footprint 0603
footprint 0603M
footprint 0603L
footprint 0603_HV
footprint 0603S
pins: 1, 2

## RC0603FR-0728K7L
designator R?  ValueDisplayed: 28.7k  (hidden comment: RC0603FR-0728K7L)
RES, 28.7 k, 1%, 0.1 W, 0603; Manufacturer: Yageo America; CompType: Resistor; Value: 28.7k; Res_ohm: 28700; Value_Code: 28k7; Tolerance_%: 1; Power_W: 0.1; Value2: 0.1W; VDC_V: 150; TempCo: 200 ppm/C; SizeArea_mm2: 1.28; SizeX_mm: 1.6; SizeY_mm: 0.8; EIA_Code: E96; U/M: EA; AEC Category: Q200
signal-integrity model Resistor
simulation model Resistor
footprint 0603
footprint 0603M
footprint 0603L
footprint 0603_HV
footprint 0603S
pins: 1, 2

## RC0603FR-0728KL
designator R?  ValueDisplayed: 28.0k  (hidden comment: RC0603FR-0728KL)
RES, 28.0 k, 1%, 0.1 W, 0603; Manufacturer: Yageo America; CompType: Resistor; Value: 28.0k; Res_ohm: 28000; Value_Code: 28k0; Tolerance_%: 1; Power_W: 0.1; Value2: 0.1W; VDC_V: 150; TempCo: 200 ppm/C; SizeArea_mm2: 1.28; SizeX_mm: 1.6; SizeY_mm: 0.8; EIA_Code: E96; U/M: EA; AEC Category: Q200
signal-integrity model Resistor
simulation model Resistor
footprint 0603
footprint 0603M
footprint 0603L
footprint 0603_HV
footprint 0603S
pins: 1, 2

## RC0603FR-0728R7L
designator R?  ValueDisplayed: 28.7  (hidden comment: RC0603FR-0728R7L)
RES, 28.7, 1%, 0.1 W, 0603; Manufacturer: Yageo America; CompType: Resistor; Value: 28.7; Value_Code: 28R7; Tolerance_%: 1; Power_W: 0.1; Value2: 0.1W; VDC_V: 150; TempCo: 200 ppm/C; SizeArea_mm2: 1.28; SizeX_mm: 1.6; SizeY_mm: 0.8; EIA_Code: E96; U/M: EA; AEC Category: Q200
signal-integrity model Resistor
simulation model Resistor
footprint 0603
footprint 0603M
footprint 0603L
footprint 0603_HV
footprint 0603S
pins: 1, 2

## RC0603FR-0728RL
designator R?  ValueDisplayed: 28.0  (hidden comment: RC0603FR-0728RL)
RES, 28.0, 1%, 0.1 W, 0603; Manufacturer: Yageo America; CompType: Resistor; Value: 28.0; Res_ohm: 28; Value_Code: 28R0; Tolerance_%: 1; Power_W: 0.1; Value2: 0.1W; VDC_V: 150; TempCo: 200 ppm/C; SizeArea_mm2: 1.28; SizeX_mm: 1.6; SizeY_mm: 0.8; EIA_Code: E96; U/M: EA; AEC Category: Q200
signal-integrity model Resistor
simulation model Resistor
footprint 0603
footprint 0603M
footprint 0603L
footprint 0603_HV
footprint 0603S
pins: 1, 2

## RC0603FR-0729K4L
designator R?  ValueDisplayed: 29.4k  (hidden comment: RC0603FR-0729K4L)
RES, 29.4 k, 1%, 0.1 W, 0603; Manufacturer: Yageo America; CompType: Resistor; Value: 29.4k; Res_ohm: 29400; Value_Code: 29k4; Tolerance_%: 1; Power_W: 0.1; Value2: 0.1W; VDC_V: 150; TempCo: 200 ppm/C; SizeArea_mm2: 1.28; SizeX_mm: 1.6; SizeY_mm: 0.8; EIA_Code: E96; U/M: EA; AEC Category: Q200; Green_Lifecycle: Active; Green_REACh: Passed
signal-integrity model Resistor
simulation model Resistor
footprint 0603
footprint 0603M
footprint 0603L
footprint 0603_HV
footprint 0603S
pins: 1, 2

## RC0603FR-0729R4L
designator R?  ValueDisplayed: 29.4  (hidden comment: RC0603FR-0729R4L)
RES, 29.4, 1%, 0.1 W, 0603; Manufacturer: Yageo America; CompType: Resistor; Value: 29.4; Value_Code: 29R4; Tolerance_%: 1; Power_W: 0.1; Value2: 0.1W; VDC_V: 150; TempCo: 200 ppm/C; SizeArea_mm2: 1.28; SizeX_mm: 1.6; SizeY_mm: 0.8; EIA_Code: E96; U/M: EA; AEC Category: Q200
signal-integrity model Resistor
simulation model Resistor
footprint 0603
footprint 0603M
footprint 0603L
footprint 0603_HV
footprint 0603S
pins: 1, 2

## RC0603FR-0730K1L
designator R?  ValueDisplayed: 30.1k  (hidden comment: RC0603FR-0730K1L)
RES, 30.1 k, 1%, 0.1 W, 0603; Manufacturer: Yageo America; CompType: Resistor; Value: 30.1k; Res_ohm: 30100; Value_Code: 30k1; Tolerance_%: 1; Power_W: 0.1; Value2: 0.1W; VDC_V: 150; TempCo: 200 ppm/C; SizeArea_mm2: 1.28; SizeX_mm: 1.6; SizeY_mm: 0.8; EIA_Code: E96; U/M: EA; AEC Category: Q200; Green_Lifecycle: Active; Green_REACh: Passed
signal-integrity model Resistor
simulation model Resistor
footprint 0603
footprint 0603M
footprint 0603L
footprint 0603_HV
footprint 0603S
pins: 1, 2

## RC0603FR-0730K9L
designator R?  ValueDisplayed: 30.9k  (hidden comment: RC0603FR-0730K9L)
RES, 30.9 k, 1%, 0.1 W, 0603; Manufacturer: Yageo America; CompType: Resistor; Value: 30.9k; Res_ohm: 30900; Value_Code: 30k9; Tolerance_%: 1; Power_W: 0.1; Value2: 0.1W; VDC_V: 150; TempCo: 200 ppm/C; SizeArea_mm2: 1.28; SizeX_mm: 1.6; SizeY_mm: 0.8; EIA_Code: E96; U/M: EA; AEC Category: Q200; Green_Lifecycle: Active; Green_REACh: Passed
signal-integrity model Resistor
simulation model Resistor
footprint 0603
footprint 0603M
footprint 0603L
footprint 0603_HV
footprint 0603S
pins: 1, 2

## RC0603FR-0730KL
designator R?  ValueDisplayed: 30.0k  (hidden comment: RC0603FR-0730KL)
RES, 30.0 k, 1%, 0.1 W, 0603; Manufacturer: Yageo America; CompType: Resistor; Value: 30.0k; Res_ohm: 30000; Value_Code: 30k0; Tolerance_%: 1; Power_W: 0.1; Value2: 0.1W; VDC_V: 150; TempCo: 200 ppm/C; SizeArea_mm2: 1.28; SizeX_mm: 1.6; SizeY_mm: 0.8; U/M: EA; AEC Category: Q200; Green_Lifecycle: Active; Green_REACh: Passed
signal-integrity model Resistor
simulation model Resistor
footprint 0603
footprint 0603M
footprint 0603L
footprint 0603_HV
footprint 0603S
pins: 1, 2

## RC0603FR-0730R1L
designator R?  ValueDisplayed: 30.1  (hidden comment: RC0603FR-0730R1L)
RES, 30.1, 1%, 0.1 W, 0603; Manufacturer: Yageo America; CompType: Resistor; Value: 30.1; Value_Code: 30R1; Tolerance_%: 1; Power_W: 0.1; Value2: 0.1W; VDC_V: 150; TempCo: 200 ppm/C; SizeArea_mm2: 1.28; SizeX_mm: 1.6; SizeY_mm: 0.8; EIA_Code: E96; U/M: EA; AEC Category: Q200
signal-integrity model Resistor
simulation model Resistor
footprint 0603
footprint 0603M
footprint 0603L
footprint 0603_HV
footprint 0603S
pins: 1, 2

## RC0603FR-0730R9L
designator R?  ValueDisplayed: 30.9  (hidden comment: RC0603FR-0730R9L)
RES, 30.9, 1%, 0.1 W, 0603; Manufacturer: Yageo America; CompType: Resistor; Value: 30.9; Value_Code: 30R9; Tolerance_%: 1; Power_W: 0.1; Value2: 0.1W; VDC_V: 150; TempCo: 200 ppm/C; SizeArea_mm2: 1.28; SizeX_mm: 1.6; SizeY_mm: 0.8; EIA_Code: E96; U/M: EA; AEC Category: Q200
signal-integrity model Resistor
simulation model Resistor
footprint 0603
footprint 0603M
footprint 0603L
footprint 0603_HV
footprint 0603S
pins: 1, 2

## RC0603FR-0730RL
designator R?  ValueDisplayed: 30.0  (hidden comment: RC0603FR-0730RL)
RES, 30.0, 1%, 0.1 W, 0603; Manufacturer: Yageo America; CompType: Resistor; Value: 30.0; Res_ohm: 30; Value_Code: 30R0; Tolerance_%: 1; Power_W: 0.1; Value2: 0.1W; VDC_V: 150; TempCo: 200 ppm/C; SizeArea_mm2: 1.28; SizeX_mm: 1.6; SizeY_mm: 0.8; U/M: EA; AEC Category: Q200
signal-integrity model Resistor
simulation model Resistor
footprint 0603
footprint 0603M
footprint 0603L
footprint 0603_HV
footprint 0603S
pins: 1, 2

## RC0603FR-0731K6L
designator R?  ValueDisplayed: 31.6k  (hidden comment: RC0603FR-0731K6L)
RES, 31.6 k, 1%, 0.1 W, 0603; Manufacturer: Yageo America; CompType: Resistor; Value: 31.6k; Res_ohm: 31600; Value_Code: 31k6; Tolerance_%: 1; Power_W: 0.1; Value2: 0.1W; VDC_V: 150; TempCo: 200 ppm/C; SizeArea_mm2: 1.28; SizeX_mm: 1.6; SizeY_mm: 0.8; EIA_Code: E96; U/M: EA; AEC Category: Q200; Green_Lifecycle: Active; Green_REACh: Passed
signal-integrity model Resistor
simulation model Resistor
footprint 0603
footprint 0603M
footprint 0603L
footprint 0603_HV
footprint 0603S
pins: 1, 2

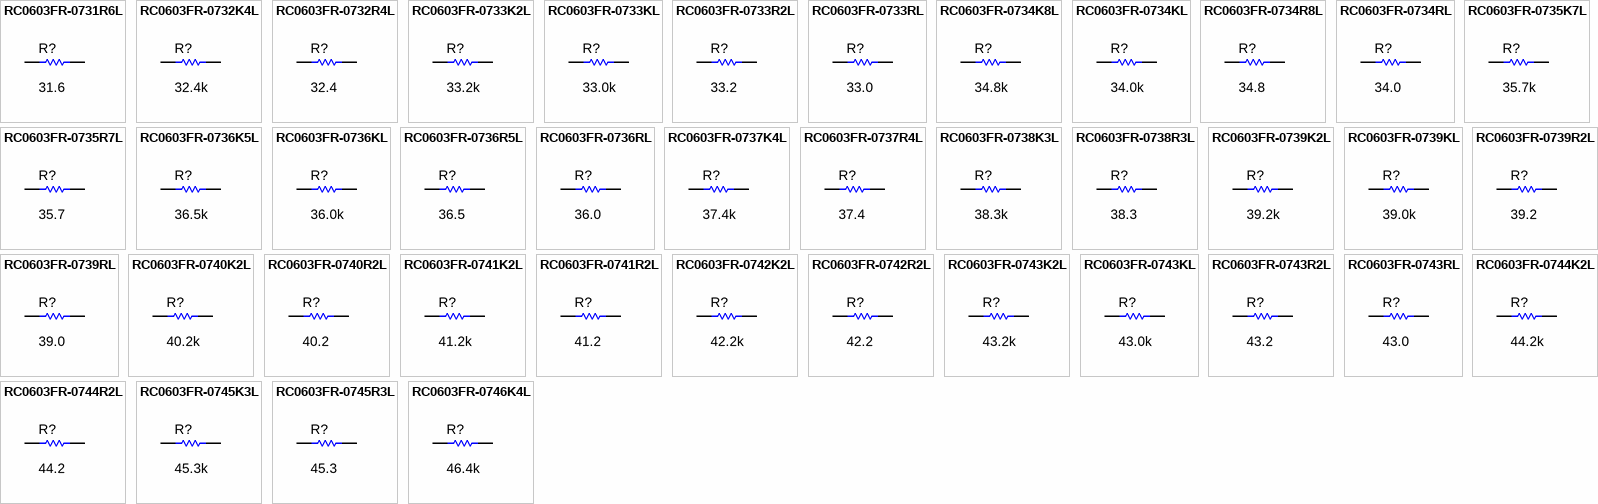
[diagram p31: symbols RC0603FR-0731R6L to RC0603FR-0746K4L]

## RC0603FR-0731R6L
designator R?  ValueDisplayed: 31.6  (hidden comment: RC0603FR-0731R6L)
RES, 31.6, 1%, 0.1 W, 0603; Manufacturer: Yageo America; CompType: Resistor; Value: 31.6; Value_Code: 31R6; Tolerance_%: 1; Power_W: 0.1; Value2: 0.1W; VDC_V: 150; TempCo: 200 ppm/C; SizeArea_mm2: 1.28; SizeX_mm: 1.6; SizeY_mm: 0.8; EIA_Code: E96; U/M: EA; AEC Category: Q200
signal-integrity model Resistor
simulation model Resistor
footprint 0603
footprint 0603M
footprint 0603L
footprint 0603_HV
footprint 0603S
pins: 1, 2

## RC0603FR-0732K4L
designator R?  ValueDisplayed: 32.4k  (hidden comment: RC0603FR-0732K4L)
RES, 32.4 k, 1%, 0.1 W, 0603; Manufacturer: Yageo America; CompType: Resistor; Value: 32.4k; Res_ohm: 32400; Value_Code: 32k4; Tolerance_%: 1; Power_W: 0.1; Value2: 0.1W; VDC_V: 150; TempCo: 200 ppm/C; SizeArea_mm2: 1.28; SizeX_mm: 1.6; SizeY_mm: 0.8; EIA_Code: E96; U/M: EA; AEC Category: Q200; Green_Lifecycle: Active; Green_REACh: Passed
signal-integrity model Resistor
simulation model Resistor
footprint 0603
footprint 0603M
footprint 0603L
footprint 0603_HV
footprint 0603S
pins: 1, 2

## RC0603FR-0732R4L
designator R?  ValueDisplayed: 32.4  (hidden comment: RC0603FR-0732R4L)
RES, 32.4, 1%, 0.1 W, 0603; Manufacturer: Yageo America; CompType: Resistor; Value: 32.4; Value_Code: 32R4; Tolerance_%: 1; Power_W: 0.1; Value2: 0.1W; VDC_V: 150; TempCo: 200 ppm/C; SizeArea_mm2: 1.28; SizeX_mm: 1.6; SizeY_mm: 0.8; EIA_Code: E96; U/M: EA; AEC Category: Q200; AEC Qualified: N
signal-integrity model Resistor
simulation model Resistor
footprint 0603
footprint 0603M
footprint 0603L
footprint 0603_HV
footprint 0603S
pins: 1, 2

## RC0603FR-0733K2L
designator R?  ValueDisplayed: 33.2k  (hidden comment: RC0603FR-0733K2L)
RES, 33.2 k, 1%, 0.1 W, 0603; Manufacturer: Yageo America; CompType: Resistor; Value: 33.2k; Res_ohm: 33200; Value_Code: 33k2; Tolerance_%: 1; Power_W: 0.1; Value2: 0.1W; VDC_V: 150; TempCo: 200 ppm/C; SizeArea_mm2: 1.28; SizeX_mm: 1.6; SizeY_mm: 0.8; EIA_Code: E96; U/M: EA; AEC Category: Q200; Green_Lifecycle: Active; Green_REACh: Passed
signal-integrity model Resistor
simulation model Resistor
footprint 0603
footprint 0603M
footprint 0603L
footprint 0603_HV
footprint 0603S
pins: 1, 2

## RC0603FR-0733KL
designator R?  ValueDisplayed: 33.0k  (hidden comment: RC0603FR-0733KL)
RES, 33.0 k, 1%, 0.1 W, 0603; Manufacturer: Yageo America; CompType: Resistor; Value: 33.0k; Res_ohm: 33000; Value_Code: 33k0; Tolerance_%: 1; Power_W: 0.1; Value2: 0.1W; VDC_V: 150; TempCo: 200 ppm/C; SizeArea_mm2: 1.28; SizeX_mm: 1.6; SizeY_mm: 0.8; U/M: EA; AEC Category: Q200; Green_Lifecycle: Active; Green_REACh: Passed
signal-integrity model Resistor
simulation model Resistor
footprint 0603
footprint 0603M
footprint 0603L
footprint 0603_HV
footprint 0603S
pins: 1, 2

## RC0603FR-0733R2L
designator R?  ValueDisplayed: 33.2  (hidden comment: RC0603FR-0733R2L)
RES, 33.2, 1%, 0.1 W, 0603; Manufacturer: Yageo America; CompType: Resistor; Value: 33.2; Value_Code: 33R2; Tolerance_%: 1; Power_W: 0.1; Value2: 0.1W; VDC_V: 150; TempCo: 200 ppm/C; SizeArea_mm2: 1.28; SizeX_mm: 1.6; SizeY_mm: 0.8; EIA_Code: E96; U/M: EA; AEC Category: Q200; Green_Lifecycle: Active; Green_REACh: Passed
signal-integrity model Resistor
simulation model Resistor
footprint 0603
footprint 0603M
footprint 0603L
footprint 0603_HV
footprint 0603S
pins: 1, 2

## RC0603FR-0733RL
designator R?  ValueDisplayed: 33.0  (hidden comment: RC0603FR-0733RL)
RES, 33.0, 1%, 0.1 W, 0603; Manufacturer: Yageo America; CompType: Resistor; Value: 33.0; Res_ohm: 33; Value_Code: 33R0; Tolerance_%: 1; Power_W: 0.1; Value2: 0.1W; VDC_V: 150; TempCo: 200 ppm/C; SizeArea_mm2: 1.28; SizeX_mm: 1.6; SizeY_mm: 0.8; U/M: EA; AEC Category: Q200; Green_Lifecycle: Active; Green_REACh: Passed
signal-integrity model Resistor
simulation model Resistor
footprint 0603
footprint 0603M
footprint 0603L
footprint 0603_HV
footprint 0603S
pins: 1, 2

## RC0603FR-0734K8L
designator R?  ValueDisplayed: 34.8k  (hidden comment: RC0603FR-0734K8L)
RES, 34.8 k, 1%, 0.1 W, 0603; Manufacturer: Yageo America; CompType: Resistor; Value: 34.8k; Res_ohm: 34800; Value_Code: 34k8; Tolerance_%: 1; Power_W: 0.1; Value2: 0.1W; VDC_V: 150; TempCo: 200 ppm/C; SizeArea_mm2: 1.28; SizeX_mm: 1.6; SizeY_mm: 0.8; EIA_Code: E96; U/M: EA; AEC Category: Q200; Green_Lifecycle: Active; Green_REACh: Passed
signal-integrity model Resistor
simulation model Resistor
footprint 0603
footprint 0603M
footprint 0603L
footprint 0603_HV
footprint 0603S
pins: 1, 2

## RC0603FR-0734KL
designator R?  ValueDisplayed: 34.0k  (hidden comment: RC0603FR-0734KL)
RES, 34.0 k, 1%, 0.1 W, 0603; Manufacturer: Yageo America; CompType: Resistor; Value: 34.0k; Res_ohm: 34000; Value_Code: 34k0; Tolerance_%: 1; Power_W: 0.1; Value2: 0.1W; VDC_V: 150; TempCo: 200 ppm/C; SizeArea_mm2: 1.28; SizeX_mm: 1.6; SizeY_mm: 0.8; EIA_Code: E96; U/M: EA; AEC Category: Q200
signal-integrity model Resistor
simulation model Resistor
footprint 0603
footprint 0603M
footprint 0603L
footprint 0603_HV
footprint 0603S
pins: 1, 2

## RC0603FR-0734R8L
designator R?  ValueDisplayed: 34.8  (hidden comment: RC0603FR-0734R8L)
RES, 34.8, 1%, 0.1 W, 0603; Manufacturer: Yageo America; CompType: Resistor; Value: 34.8; Value_Code: 34R8; Tolerance_%: 1; Power_W: 0.1; Value2: 0.1W; VDC_V: 150; TempCo: 200 ppm/C; SizeArea_mm2: 1.28; SizeX_mm: 1.6; SizeY_mm: 0.8; EIA_Code: E96; U/M: EA; AEC Category: Q200; Green_Lifecycle: Active; Green_REACh: Passed
signal-integrity model Resistor
simulation model Resistor
footprint 0603
footprint 0603M
footprint 0603L
footprint 0603_HV
footprint 0603S
pins: 1, 2

## RC0603FR-0734RL
designator R?  ValueDisplayed: 34.0  (hidden comment: RC0603FR-0734RL)
RES, 34.0, 1%, 0.1 W, 0603; Manufacturer: Yageo America; CompType: Resistor; Value: 34.0; Res_ohm: 34; Value_Code: 34R0; Tolerance_%: 1; Power_W: 0.1; Value2: 0.1W; VDC_V: 150; TempCo: 200 ppm/C; SizeArea_mm2: 1.28; SizeX_mm: 1.6; SizeY_mm: 0.8; EIA_Code: E96; U/M: EA; AEC Category: Q200
signal-integrity model Resistor
simulation model Resistor
footprint 0603
footprint 0603M
footprint 0603L
footprint 0603_HV
footprint 0603S
pins: 1, 2

## RC0603FR-0735K7L
designator R?  ValueDisplayed: 35.7k  (hidden comment: RC0603FR-0735K7L)
RES, 35.7 k, 1%, 0.1 W, 0603; Manufacturer: Yageo America; CompType: Resistor; Value: 35.7k; Res_ohm: 35700; Value_Code: 35k7; Tolerance_%: 1; Power_W: 0.1; Value2: 0.1W; VDC_V: 150; TempCo: 200 ppm/C; SizeArea_mm2: 1.28; SizeX_mm: 1.6; SizeY_mm: 0.8; EIA_Code: E96; U/M: EA; AEC Category: Q200; Green_Lifecycle: Active; Green_REACh: Passed
signal-integrity model Resistor
simulation model Resistor
footprint 0603
footprint 0603M
footprint 0603L
footprint 0603_HV
footprint 0603S
pins: 1, 2

## RC0603FR-0735R7L
designator R?  ValueDisplayed: 35.7  (hidden comment: RC0603FR-0735R7L)
RES, 35.7, 1%, 0.1 W, 0603; Manufacturer: Yageo America; CompType: Resistor; Value: 35.7; Value_Code: 35R7; Tolerance_%: 1; Power_W: 0.1; Value2: 0.1W; VDC_V: 150; TempCo: 200 ppm/C; SizeArea_mm2: 1.28; SizeX_mm: 1.6; SizeY_mm: 0.8; EIA_Code: E96; U/M: EA; AEC Category: Q200
signal-integrity model Resistor
simulation model Resistor
footprint 0603
footprint 0603M
footprint 0603L
footprint 0603_HV
footprint 0603S
pins: 1, 2

## RC0603FR-0736K5L
designator R?  ValueDisplayed: 36.5k  (hidden comment: RC0603FR-0736K5L)
RES, 36.5 k, 1%, 0.1 W, 0603; Manufacturer: Yageo America; CompType: Resistor; Value: 36.5k; Res_ohm: 36500; Value_Code: 36k5; Tolerance_%: 1; Power_W: 0.1; Value2: 0.1W; VDC_V: 150; TempCo: 200 ppm/C; SizeArea_mm2: 1.28; SizeX_mm: 1.6; SizeY_mm: 0.8; EIA_Code: E96; U/M: EA; AEC Category: Q200
signal-integrity model Resistor
simulation model Resistor
footprint 0603
footprint 0603M
footprint 0603L
footprint 0603_HV
footprint 0603S
pins: 1, 2

## RC0603FR-0736KL
designator R?  ValueDisplayed: 36.0k  (hidden comment: RC0603FR-0736KL)
RES, 36.0 k, 1%, 0.1 W, 0603; Manufacturer: Yageo America; CompType: Resistor; Value: 36.0k; Res_ohm: 36000; Value_Code: 36k0; Tolerance_%: 1; Power_W: 0.1; Value2: 0.1W; VDC_V: 150; TempCo: 200 ppm/C; SizeArea_mm2: 1.28; SizeX_mm: 1.6; SizeY_mm: 0.8; U/M: EA; AEC Category: Q200; Green_Lifecycle: Active; Green_REACh: Passed
signal-integrity model Resistor
simulation model Resistor
footprint 0603
footprint 0603M
footprint 0603L
footprint 0603_HV
footprint 0603S
pins: 1, 2

## RC0603FR-0736R5L
designator R?  ValueDisplayed: 36.5  (hidden comment: RC0603FR-0736R5L)
RES, 36.5, 1%, 0.1 W, 0603; Manufacturer: Yageo America; CompType: Resistor; Value: 36.5; Value_Code: 36R5; Tolerance_%: 1; Power_W: 0.1; Value2: 0.1W; VDC_V: 150; TempCo: 200 ppm/C; SizeArea_mm2: 1.28; SizeX_mm: 1.6; SizeY_mm: 0.8; EIA_Code: E96; U/M: EA; AEC Category: Q200
signal-integrity model Resistor
simulation model Resistor
footprint 0603
footprint 0603M
footprint 0603L
footprint 0603_HV
footprint 0603S
pins: 1, 2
